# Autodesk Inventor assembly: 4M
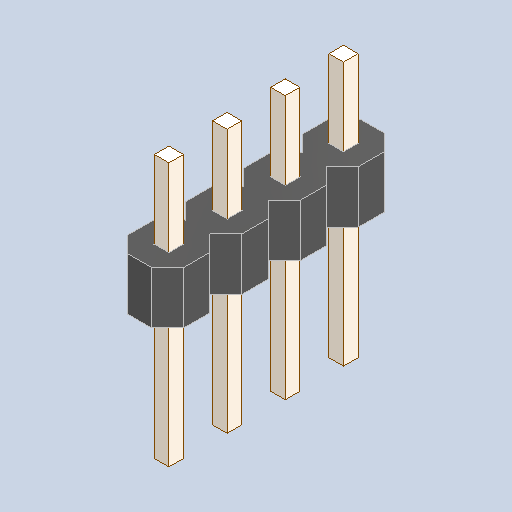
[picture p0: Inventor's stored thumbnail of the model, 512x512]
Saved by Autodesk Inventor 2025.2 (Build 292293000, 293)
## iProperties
Created: 2025-04
Part Number: 4M
Description: PART--DESC
Document SubType Name: Assembly
Designer: BennF
Author: BennF
Revision Number: NONE
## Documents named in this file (3)
- C:\Users\BennF\Nextcloud\Benutzer\CNC JarBeRi\existing parts\Electronics\RepRap A4988 Shied (USE WITHOUT ARDUINO)\reprap-a4988-1.snapshot.1\RepRap\RepRap\4M.iam
- C:\Users\BennF\Nextcloud\Benutzer\CNC JarBeRi\existing parts\Electronics\RepRap A4988 Shied (USE WITHOUT ARDUINO)\reprap-a4988-1.snapshot.1\RepRap\RepRap\4M Geometry.ipt
- C:\Users\BennF\Nextcloud\Benutzer\CNC JarBeRi\existing parts\Electronics\RepRap A4988 Shied (USE WITHOUT ARDUINO)\reprap-a4988-1.snapshot.1\RepRap\RepRap\Pin5.ipt
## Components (2 placed, 2 different names)
1. 4M Geometry
2. Pin5
